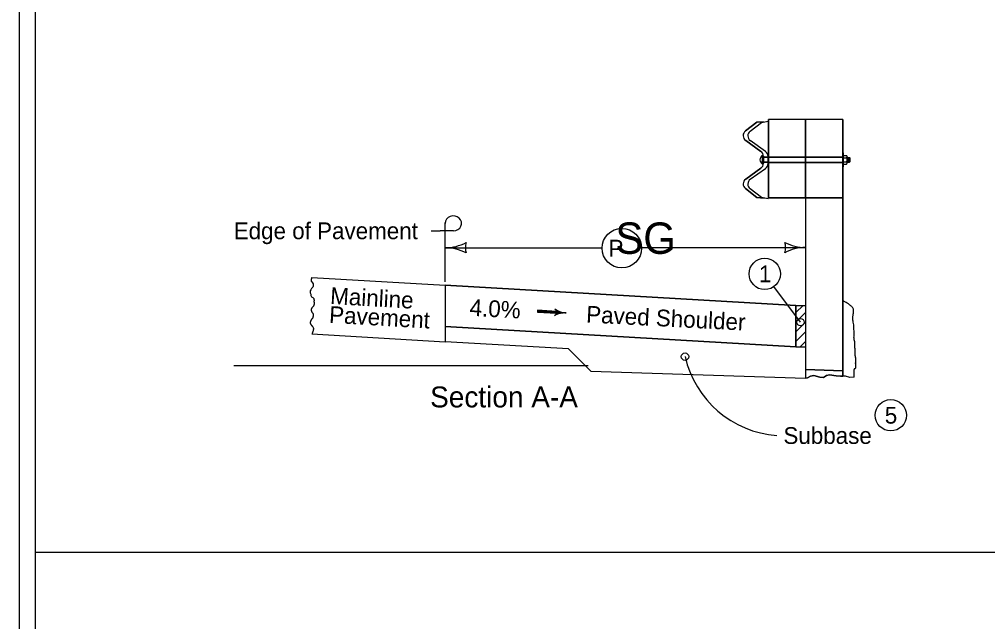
# Model space of a CAD drawing. Extents: x 9538 to 81668, y 7600 to 11751.
# Drawn here: x 10133 to 11058, y 8774 to 9349 of the extents above; entities that cross this region are included whole.
import ezdxf

# ---------------------------------------------------------------- set-up
doc = ezdxf.new("R2010")
doc.units = 0
for name, color, linetype in [('Default', 7, 'Continuous'), ('DsnShtMinorGrid13', 7, 'Continuous'), ('DsnShtMinorGrid14', 7, 'Continuous'), ('dsnStdCells', 7, 'Continuous'), ('dsnStdDimension', 7, 'Continuous'), ('dsnStdNameDate', 7, 'Continuous'), ('dsnStdNote', 7, 'Continuous'), ('dsnStdShading', 7, 'Continuous'), ('dsnStdTable', 7, 'Continuous')]:
    doc.layers.add(name, color=color, linetype=linetype)

msp = doc.modelspace()

# ---------------------------------------------------------------- linework, layer by layer
at = {"layer": 'Default'}
msp.add_lwpolyline([(10132.52, 9944.02), (13267.53, 9944.02), (13267.53, 7924.02), (10132.52, 7924.02)], close=True, dxfattribs=at)
at = {"layer": 'DsnShtMinorGrid13'}
for centre, radius in [((10844.79, 9106.23), 15), ((10878.91, 9060.11), 3.58), ((10965.23, 8971.18), 15)]:
    msp.add_circle(centre, radius, dxfattribs=at)
at = {"layer": 'DsnShtMinorGrid14'}
msp.add_circle((10768.59, 9027.15), 3.54, dxfattribs=at)
at = {"layer": 'dsnStdCells'}
for p, q in [((10826.55, 9233.67), (10841.06, 9223.26)), ((10841.06, 9207.18), (10826.55, 9196.77))]:
    msp.add_line(p, q, dxfattribs=at)
for points in [[(10883.85, 9217.88), (10883.85, 9253.55), (10848.3, 9253.55), (10848.3, 9217.88), (10848.3, 9217.88), (10883.85, 9217.88)], [(10919.39, 9217.88), (10919.39, 9221.88), (10919.39, 9253.55), (10883.85, 9253.55), (10883.85, 9217.88), (10919.39, 9217.88)], [(10830.8, 9242.57), (10830.79, 9242.56), (10841.57, 9250.97), (10843.45, 9251.3), (10837.12, 9251.19), (10826.36, 9242.79)], [(10845.51, 9223.04), (10845.54, 9223.02), (10830.97, 9233.48), (10831, 9233.45)], [(10843.46, 9218.63), (10843.46, 9217.55), (10847.9, 9217.55), (10847.9, 9218.41), (10847.9, 9218.41)], [(10848.3, 9217.55), (10848.3, 9212.88), (10848.3, 9212.88), (10883.85, 9212.88), (10883.85, 9217.55), (10848.3, 9217.55), (10848.3, 9217.55)], [(10919.39, 9212.88), (10919.39, 9217.55), (10883.85, 9217.55), (10883.85, 9212.88), (10919.39, 9212.88)], [(10831, 9196.55), (10830.97, 9196.53), (10845.54, 9206.99), (10845.51, 9206.96)], [(10847.9, 9211.6), (10847.9, 9211.6), (10847.9, 9212.88), (10843.46, 9212.88), (10843.46, 9211.82), (10843.46, 9212.88), (10843.46, 9212.88), (10843.46, 9211.82)], [(10848.3, 9212.55), (10848.3, 9178.9), (10883.85, 9178.9), (10883.85, 9212.55), (10848.3, 9212.55)], [(10919.39, 9178.9), (10919.39, 9208.55), (10919.39, 9212.55), (10883.85, 9212.55), (10883.85, 9178.9), (10919.39, 9178.9)], [(10826.36, 9187.65), (10837.12, 9179.25), (10844.23, 9178.56), (10841.57, 9179.03), (10830.79, 9187.44), (10830.8, 9187.43)], [(10919.39, 9013.57), (10919.39, 9178.9), (10883.85, 9178.9), (10883.85, 9075.94), (10883.85, 9069.25), (10883.85, 9069.25), (10883.85, 9069.25), (10883.85, 9060.02), (10883.85, 9060.02), (10883.85, 9060.02), (10883.85, 9050.88), (10883.85, 9050.88), (10883.85, 9050.88), (10883.85, 9043.95), (10883.85, 9014.73), (10919.39, 9013.57)], [(10919.39, 9013.57), (10883.85, 9014.73), (10883.85, 9006.67), (10885.66, 9006.92), (10888.41, 9008.51), (10891.7, 9009.04), (10897.32, 9007.45), (10901.03, 9007.24), (10903.68, 9009.04), (10906.75, 9009.68), (10913, 9008.94), (10917.24, 9008.51), (10919.39, 9008.51), (10919.39, 9013.57)]]:
    msp.add_lwpolyline(points, dxfattribs=at)
msp.add_lwpolyline([(10847.9, 9217.55), (10843.46, 9217.55), (10843.46, 9214.09), (10843.46, 9215.22), (10843.46, 9212.88), (10847.9, 9212.88)], close=True, dxfattribs=at)
for centre, start, end in [((10829.83, 9238.31), 127.75002, 234.69086), ((10834.28, 9238.09), 127.75002, 234.69086), ((10837.78, 9218.63), 0, 54.69099), ((10842.23, 9218.41), 0, 54.69099), ((10837.78, 9211.82), 305.30901, 0), ((10842.23, 9211.6), 305.30901, 0), ((10829.83, 9192.14), 125.30914, 232.24998), ((10834.28, 9191.92), 125.30914, 232.24998)]:
    msp.add_arc(centre, 5.68, start, end, dxfattribs=at)
at = {"layer": 'dsnStdDimension'}
for p, q in [((10539.46, 9131.19), (10689.29, 9131.19)), ((10727.14, 9131.34), (10883.85, 9131.34))]:
    msp.add_line(p, q, dxfattribs=at)
msp.add_circle((10708.21, 9130.78), 18.93, dxfattribs=at)
for centre, radius, start, end in [((10539.46, 9173.69), 42.5, 270, 298.07249), ((10575.09, 9131.19), 16.42, 162.26665, 197.73335), ((10848.21, 9131.34), 16.42, 342.26665, 17.73335), ((10883.85, 9173.84), 42.5, 241.92751, 270), ((10539.46, 9088.69), 42.5, 61.92751, 90), ((10883.85, 9088.84), 42.5, 90, 118.07249), ((10863.82, 9049.27), 97.76, 193.07698, 265.55799)]:
    msp.add_arc(centre, radius, start, end, dxfattribs=at)
at = {"layer": 'dsnStdNameDate'}
for p, q in [((10874.59, 9075.94), (10539.46, 9095.43)), ((10539.46, 9095.43), (10539.46, 9055.83)), ((10878.91, 9060.11), (10853.53, 9094.04)), ((10874.59, 9036.51), (10874.59, 9075.94)), ((10539.46, 9055.83), (10874.59, 9036.51)), ((12303.1, 8840.02), (10147.52, 8840.02))]:
    msp.add_line(p, q, dxfattribs=at)
at = {"layer": 'dsnStdNote'}
for p, q in [((10539.46, 9134.51), (10539.46, 9155.37)), ((10526.09, 9147.35), (10534.77, 9147.35)), ((10547.27, 9147.35), (10534.77, 9147.35)), ((10539.46, 9098.57), (10539.46, 9134.51)), ((10645.84, 9069.47), (10627.63, 9070.52)), ((10645.74, 9068.53), (10645.74, 9068.53)), ((10645.85, 9070.47), (10645.85, 9070.47))]:
    msp.add_line(p, q, dxfattribs=at)
for points in [[(10645.87, 9070.41), (10627.7, 9071.46), (10627.57, 9069.58), (10645.74, 9068.53), (10645.79, 9070.14), (10627.92, 9071.23), (10627.86, 9069.74), (10645.35, 9068.79), (10645.48, 9069.91), (10628.15, 9070.97), (10628.13, 9069.97), (10645.14, 9068.99), (10645.23, 9069.69), (10628.34, 9070.75), (10628.33, 9070.19), (10644.93, 9069.25)], [(10645.46, 9071.66), (10646.16, 9070.5), (10646.13, 9068.85), (10645.38, 9067.45), (10648.13, 9068.32), (10651.33, 9068.97), (10652.23, 9069.1), (10649.98, 9069.65), (10646.75, 9070.88), (10645.81, 9071.41), (10645.93, 9067.9), (10650.88, 9069.12), (10646.24, 9070.7), (10646.25, 9068.28), (10649.65, 9069.21), (10646.65, 9070.07), (10646.42, 9068.69), (10648.58, 9069.19), (10646.99, 9069.7), (10646.86, 9069.04), (10647.64, 9069.2)]]:
    msp.add_lwpolyline(points, dxfattribs=at)
for centre, major_axis, start_param, end_param in [((10547.27, 9154.49), (-7.81, 0), 1.570796, 6.283185), ((10642.07, 9069.68), (3.88, 0), 5.202895, 7.237436), ((10654.34, 9048.69), (22.17, 0), 1.537172, 2.061295), ((10657.13, 9089.11), (-22.17, 0), 0.954258, 1.478381)]:
    msp.add_ellipse(centre, major_axis=major_axis, ratio=0.913811, start_param=start_param, end_param=end_param, dxfattribs=at)
at = {"layer": 'dsnStdShading'}
msp.add_line((10147.52, 9929.02), (10147.52, 8319.02), dxfattribs=at)
at = {"layer": 'dsnStdTable'}
for p, q in [((10919.39, 9253.55), (10848.3, 9253.55)), ((10848.3, 9178.9), (10848.3, 9253.55)), ((10883.85, 9178.9), (10883.85, 9253.55)), ((10919.39, 9253.55), (10919.39, 9008.51)), ((10826.36, 9242.79), (10837.12, 9251.19)), ((10830.79, 9242.56), (10841.57, 9250.97)), ((10837.12, 9251.19), (10843.45, 9251.3)), ((10841.57, 9250.97), (10847.9, 9252.09)), ((10841.06, 9223.26), (10826.55, 9233.67)), ((10845.54, 9223.02), (10830.97, 9233.48)), ((10842.69, 9211.15), (10842.69, 9219.24)), ((10842.69, 9217.55), (10848.11, 9217.55)), ((10843.46, 9211.82), (10843.46, 9218.63)), ((10843.46, 9211.82), (10843.46, 9215.22)), ((10843.46, 9215.22), (10843.46, 9211.82)), ((10843.63, 9217.55), (10848.3, 9217.55)), ((10847.9, 9215), (10847.9, 9218.41)), ((10848.3, 9217.88), (10919.39, 9217.88)), ((10848.3, 9217.55), (10919.39, 9217.55)), ((10919.39, 9221.85), (10920.07, 9221.85)), ((10920.07, 9208.52), (10920.07, 9221.85)), ((10920.07, 9219.23), (10923.04, 9219.23)), ((10920.07, 9217.2), (10923.04, 9217.2)), ((10923.41, 9212.15), (10923.41, 9218.21)), ((10923.41, 9217.52), (10925.78, 9217.52)), ((10924.3, 9217.52), (10924.3, 9212.85)), ((10925.04, 9217.52), (10925.04, 9212.85)), ((10925.78, 9217.52), (10926.22, 9216.98)), ((10925.78, 9217.52), (10925.78, 9212.85)), ((10926.22, 9216.98), (10926.22, 9213.39)), ((10826.55, 9196.77), (10841.06, 9207.18)), ((10830.97, 9196.53), (10845.54, 9206.99)), ((10842.69, 9212.88), (10848.3, 9212.88)), ((10847.9, 9211.6), (10847.9, 9215)), ((10847.9, 9215), (10847.9, 9211.6)), ((10848.29, 9212.55), (10919.39, 9212.55)), ((10848.3, 9212.88), (10919.39, 9212.88)), ((10919.39, 9208.52), (10920.07, 9208.52)), ((10920.07, 9213.16), (10923.04, 9213.16)), ((10920.07, 9211.14), (10923.04, 9211.14)), ((10923.41, 9212.85), (10925.78, 9212.85)), ((10926.22, 9213.39), (10925.78, 9212.85)), ((10837.12, 9179.25), (10826.36, 9187.65)), ((10841.57, 9179.03), (10830.79, 9187.44)), ((10844.23, 9178.56), (10837.12, 9179.25)), ((10847.9, 9177.92), (10841.57, 9179.03)), ((10883.85, 9178.9), (10848.3, 9178.9)), ((10883.85, 9178.9), (10883.85, 9006.67)), ((10411.99, 9102.84), (10539.46, 9095.43)), ((10539.46, 9095.43), (10539.46, 9041.42)), ((10539.46, 9095.43), (10874.59, 9075.94)), ((10874.59, 9069.2), (10881.34, 9075.94)), ((10874.59, 9069.2), (10881.34, 9075.94)), ((10874.59, 9069.2), (10881.34, 9075.94)), ((10874.59, 9069.2), (10881.34, 9075.94)), ((10874.59, 9075.94), (10883.83, 9075.94)), ((10874.59, 9075.94), (10874.59, 9036.51)), ((10874.59, 9060.01), (10883.83, 9069.25)), ((10874.59, 9060.01), (10883.83, 9069.25)), ((10874.59, 9060.01), (10883.83, 9069.25)), ((10874.59, 9060.01), (10883.83, 9069.25)), ((10929.44, 9069.17), (10929.44, 9069.17)), ((10874.59, 9050.78), (10883.83, 9060.02)), ((10874.59, 9050.78), (10883.83, 9060.02)), ((10874.59, 9050.78), (10883.83, 9060.02)), ((10874.59, 9050.78), (10883.83, 9060.02)), ((10412.02, 9048.83), (10539.46, 9041.42)), ((10874.59, 9036.51), (10539.46, 9055.83)), ((10874.59, 9041.56), (10883.83, 9050.79)), ((10657.29, 9034.62), (10539.46, 9041.42)), ((10878.69, 9036.51), (10883.83, 9041.65)), ((10657.29, 9034.62), (10678.63, 9013.41)), ((10874.59, 9036.51), (10883.83, 9036.51)), ((10337.4, 9018.58), (10675.9, 9018.58)), ((10678.63, 9013.41), (10883.85, 9006.67))]:
    msp.add_line(p, q, dxfattribs=at)
for points in [[(10923.1, 9217.21), (10923.18, 9217.25), (10923.25, 9217.35), (10923.33, 9217.57), (10923.39, 9217.86), (10923.39, 9215.91), (10923.33, 9216.43), (10923.28, 9216.8), (10923.16, 9217.12), (10923.11, 9217.21), (10923.16, 9217.21), (10923.27, 9217.36), (10923.35, 9217.59), (10923.37, 9217.74), (10923.38, 9216.2), (10923.3, 9216.7), (10923.25, 9216.96), (10923.14, 9217.18), (10923.17, 9217.2), (10923.31, 9217.41), (10923.35, 9217.57), (10923.36, 9216.46), (10923.17, 9217.17), (10923.33, 9217.45), (10923.34, 9216.6), (10923.19, 9217.16), (10923.31, 9217.38), (10923.32, 9216.74), (10923.21, 9217.14), (10923.3, 9217.32), (10923.3, 9216.9), (10923.23, 9217.13), (10923.28, 9217.25), (10923.28, 9217.04), (10923.25, 9217.11), (10923.26, 9217.16)], [(10923.39, 9212.48), (10923.35, 9212.74), (10923.3, 9212.92), (10923.21, 9213.07), (10923.09, 9213.17), (10923.17, 9213.26), (10923.26, 9213.49), (10923.31, 9213.8), (10923.39, 9214.55), (10923.39, 9212.47), (10923.37, 9212.62), (10923.33, 9212.83), (10923.25, 9213.04), (10923.14, 9213.15), (10923.17, 9213.24), (10923.23, 9213.39), (10923.34, 9213.89), (10923.38, 9214.27), (10923.37, 9212.67), (10923.35, 9212.79), (10923.3, 9212.95), (10923.17, 9213.15), (10923.23, 9213.32), (10923.3, 9213.66), (10923.36, 9213.98), (10923.35, 9212.82), (10923.31, 9212.95), (10923.2, 9213.14), (10923.24, 9213.36), (10923.3, 9213.62), (10923.34, 9213.79), (10923.33, 9212.93), (10923.27, 9213.03), (10923.23, 9213.15), (10923.31, 9213.61), (10923.31, 9213.01), (10923.24, 9213.14), (10923.29, 9213.44), (10923.29, 9213.08), (10923.26, 9213.15), (10923.27, 9213.25), (10923.27, 9213.18)], [(10929.91, 9045.33), (10929.85, 9045.06), (10929.85, 9044.86), (10929.85, 9044.67), (10929.85, 9044.47), (10929.85, 9044.28), (10929.85, 9044.08), (10929.85, 9043.79), (10929.85, 9043.59), (10929.95, 9043.3), (10930.05, 9043.01), (10930.24, 9042.81), (10930.24, 9042.62), (10930.34, 9042.42), (10930.34, 9042.23), (10930.34, 9042.03), (10930.44, 9041.93), (10930.44, 9041.74), (10930.44, 9041.54), (10930.44, 9041.35), (10930.44, 9041.15), (10930.44, 9040.96), (10930.44, 9040.66), (10930.44, 9040.37), (10930.44, 9040.17), (10930.44, 9039.88), (10930.44, 9039.69), (10930.44, 9039.49), (10930.54, 9039.39), (10930.54, 9039.2), (10930.54, 9039), (10930.54, 9038.81), (10930.54, 9038.61), (10930.54, 9038.42), (10930.54, 9038.22), (10930.54, 9038.02), (10930.54, 9037.83), (10930.54, 9037.63), (10930.54, 9037.44), (10930.54, 9037.24), (10930.54, 9037.05), (10930.54, 9036.85), (10930.54, 9036.66), (10930.54, 9036.46), (10930.54, 9036.27), (10930.54, 9036.07), (10930.54, 9035.88), (10930.64, 9035.78), (10930.64, 9035.58), (10930.64, 9035.39), (10930.73, 9035.29), (10930.73, 9035.09), (10930.73, 9034.9), (10930.83, 9034.8), (10930.83, 9034.61), (10930.83, 9034.41), (10930.83, 9034.21), (10930.83, 9033.92), (10930.93, 9033.63), (10930.93, 9033.43), (10930.93, 9033.24), (10930.93, 9033.04), (10930.93, 9032.85), (10930.93, 9032.65), (10930.93, 9032.46), (10930.93, 9032.26), (10930.93, 9032.06), (10930.93, 9031.87), (10930.93, 9031.67), (10930.93, 9031.48), (10930.93, 9031.28), (10930.93, 9031.09), (10930.93, 9030.89), (10930.93, 9030.7), (10930.93, 9030.5), (10930.93, 9030.31), (10930.93, 9030.11), (10930.93, 9029.92), (10930.93, 9029.72), (10930.93, 9029.52), (10930.93, 9029.33), (10930.93, 9029.13), (10930.93, 9028.94), (10930.93, 9028.74), (10930.93, 9028.55), (10930.93, 9028.35), (10930.93, 9028.16), (10930.93, 9027.96), (10931.03, 9027.86), (10931.03, 9027.57), (10931.03, 9027.37), (10931.12, 9027.18), (10931.22, 9026.89), (10931.22, 9026.69), (10931.32, 9026.59), (10931.32, 9026.4), (10931.42, 9026.3), (10931.52, 9026.2), (10931.52, 9026.01), (10931.52, 9025.81), (10931.52, 9025.62), (10931.61, 9025.52), (10931.61, 9025.32), (10931.61, 9025.13), (10931.61, 9024.93), (10931.61, 9024.74), (10931.61, 9024.54), (10931.61, 9024.35), (10931.61, 9024.15), (10931.61, 9023.96), (10931.61, 9023.76), (10931.61, 9023.56), (10931.61, 9023.37), (10931.61, 9023.17), (10931.61, 9022.98), (10931.61, 9022.78), (10931.61, 9022.59), (10931.61, 9022.39), (10931.61, 9022.2), (10931.61, 9022), (10931.61, 9021.81), (10931.61, 9021.61), (10931.61, 9021.42), (10931.61, 9021.22), (10931.61, 9021.02), (10931.61, 9020.83), (10931.61, 9020.63), (10931.61, 9020.63), (10931.61, 9020.93), (10931.61, 9021.12), (10931.61, 9021.32), (10931.61, 9021.12), (10931.61, 9020.93), (10931.61, 9020.73), (10931.61, 9020.54), (10931.61, 9020.34), (10931.61, 9020.14), (10931.61, 9019.95), (10931.61, 9019.75), (10931.61, 9019.56), (10931.61, 9019.36), (10931.61, 9019.17), (10931.61, 9018.97), (10931.61, 9018.78), (10931.61, 9018.58), (10931.61, 9018.39), (10931.52, 9018.29), (10931.52, 9018.09), (10931.52, 9017.9), (10931.52, 9017.7), (10931.52, 9017.51), (10931.52, 9017.31), (10931.52, 9017.12), (10931.52, 9016.92), (10931.52, 9016.73), (10931.52, 9016.53), (10931.52, 9016.33), (10931.42, 9016.24), (10931.32, 9016.04), (10931.22, 9015.94), (10931.12, 9015.85), (10931.03, 9015.75), (10930.83, 9015.65), (10930.64, 9015.65), (10930.54, 9015.55), (10930.44, 9015.46), (10930.34, 9015.36), (10930.15, 9015.26), (10930.05, 9015.16), (10930.05, 9014.97), (10929.95, 9014.87), (10929.95, 9014.67), (10929.95, 9014.48), (10929.95, 9014.28), (10929.95, 9007.46)], [(10930.08, 9007.47), (10925.93, 9007.35), (10921.8, 9008.51), (10917.24, 9008.51), (10913, 9008.94), (10906.75, 9009.68), (10903.68, 9009.04), (10901.03, 9007.24), (10897.32, 9007.45), (10891.7, 9009.04), (10888.41, 9008.51), (10885.66, 9006.92), (10883.85, 9006.67)]]:
    msp.add_lwpolyline(points, dxfattribs=at)
for centre, radius, start, end in [((10829.83, 9238.31), 5.68, 127.75002, 234.69086), ((10834.28, 9238.09), 5.68, 127.75002, 234.69086), ((10844.76, 9215.2), 4.54, 117.20289, 242.8461), ((10837.78, 9218.63), 5.68, 360, 54.69099), ((10842.23, 9218.41), 5.68, 360, 54.69099), ((10837.78, 9211.82), 5.68, 305.30901, 0), ((10842.23, 9211.6), 5.68, 305.30901, 0), ((10829.83, 9192.14), 5.68, 125.30914, 232.24998), ((10834.28, 9191.92), 5.68, 125.30914, 232.24998)]:
    msp.add_arc(centre, radius, start, end, dxfattribs=at)
for centre in [(10923.04, 9218.21), (10923.04, 9212.15)]:
    msp.add_ellipse(centre, major_axis=(0, -1.01), ratio=0.362258, start_param=6.283156, end_param=9.424748, dxfattribs=at)
for points in [[(10411.99, 9102.84), (10411.49, 9099.24), (10412.53, 9097.73), (10413.39, 9095.44), (10412.79, 9093.38), (10410.88, 9091), (10410.36, 9089.1), (10410.88, 9086.8), (10411.75, 9084.43), (10412.79, 9083.72), (10414.17, 9081.18), (10414.16, 9080.34)], [(10412.2, 9063.23), (10412.41, 9063.48), (10412.61, 9063.74), (10412.96, 9064.3), (10413.25, 9064.89), (10413.36, 9065.19), (10413.46, 9065.51), (10413.59, 9066.13), (10413.64, 9066.75), (10413.6, 9067.34), (10413.54, 9067.61), (10413.5, 9067.75), (10413.45, 9067.88), (10413.24, 9068.26), (10412.96, 9068.62), (10412.66, 9068.99), (10412.41, 9069.38), (10412.27, 9069.67), (10412.13, 9069.95), (10411.87, 9070.52), (10411.67, 9071.09), (10411.6, 9071.38), (10411.55, 9071.68), (10411.54, 9071.81), (10411.53, 9071.94), (10411.69, 9072.71), (10411.9, 9073.23), (10412.15, 9073.74), (10412.6, 9074.38), (10413.12, 9074.92), (10413.63, 9075.47), (10413.86, 9075.78), (10414.06, 9076.12), (10414.27, 9076.59), (10414.42, 9077.06), (10414.53, 9077.54), (10414.56, 9077.78), (10414.57, 9077.9), (10414.58, 9078.02), (10414.53, 9078.53), (10414.38, 9079.04), (10414.33, 9079.17), (10414.27, 9079.29), (10414.23, 9079.42), (10414.2, 9079.55), (10414.16, 9080.34)], [(10929.91, 9045.33), (10930.23, 9048.24), (10930.01, 9053.1), (10929.57, 9058.85), (10928.91, 9063.27), (10929.13, 9066.59), (10929.57, 9070.79), (10928.91, 9073.89), (10926.7, 9075.88), (10924.71, 9077.65), (10922.49, 9078.75), (10920.28, 9080.08), (10919.4, 9080.74)], [(10412.2, 9063.23), (10411.99, 9062.99), (10411.74, 9062.76), (10411.5, 9062.52), (10411.32, 9062.25), (10411.18, 9061.97), (10411.04, 9061.68), (10410.78, 9061.11), (10410.67, 9060.83), (10410.58, 9060.54), (10410.5, 9060.25), (10410.48, 9060.1), (10410.46, 9059.95), (10410.47, 9059.44), (10410.6, 9058.92), (10410.81, 9058.4), (10411.06, 9057.89), (10411.51, 9057.26), (10412.03, 9056.71), (10412.54, 9056.16), (10412.77, 9055.86), (10412.97, 9055.52), (10413.37, 9054.57), (10413.48, 9054.1), (10413.49, 9053.62), (10413.45, 9053.33), (10413.41, 9053.04), (10413.35, 9052.75), (10413.28, 9052.47), (10412.97, 9051.32), (10412.79, 9050.71), (10412.59, 9050.11), (10412.37, 9049.52), (10412.24, 9049.23), (10412.1, 9048.94), (10412.02, 9048.83)]]:
    msp.add_spline(points, degree=3, dxfattribs=at)

# ---------------------------------------------------------------- texts
at = {"layer": 'DsnShtMinorGrid13'}
for s, p in [('1', (10839.16, 9098.23)), ('5', (10959.46, 8963.18))]:
    msp.add_text(s, height=16, dxfattribs=at).set_placement(p)
at = {"layer": 'dsnStdDimension'}
for s, height, p in [('SG', 30, (10701.93, 9125.34)), ('P', 16, (10695.5, 9122.78))]:
    msp.add_text(s, height=height, dxfattribs=at).set_placement(p)
at = {"layer": 'dsnStdNote'}
for s, height, p in [('Edge of Pavement', 16, (10337.32, 9139.35)), ('Section A-A', 20, (10525.03, 8978.66)), ('Subbase', 16, (10862.6, 8943.8))]:
    msp.add_text(s, height=height, dxfattribs=at).set_placement(p)
for s, rotation, p in [('Mainline', 356.73462, (10429.21, 9077.5)), ('4.0%', 356.69917, (10562.38, 9066.3)), ('Pavement', 356.73462, (10428.19, 9059.53)), ('Paved Shoulder ', 357.0678, (10673.85, 9059.83))]:
    msp.add_text(s, height=16, rotation=rotation, dxfattribs=at).set_placement(p)

doc.saveas('drawing.dxf')
